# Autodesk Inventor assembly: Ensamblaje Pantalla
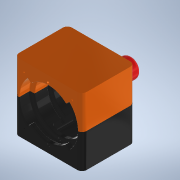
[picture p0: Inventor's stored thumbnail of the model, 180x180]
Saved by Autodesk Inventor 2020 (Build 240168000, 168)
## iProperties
Created: 2022-09
Part Number: Ensamblaje Pantalla
Document SubType Name: Assembly
Designer: SEBAS
Author: SEBAS
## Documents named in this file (3)
- D:\TRABAJO UNIVERSIDAD\PANTALLA LED INVENTOR\Ensamblaje Pantalla.iam
- D:\TRABAJO UNIVERSIDAD\MOLDER LATEAL\MOLDE LATERAL.ipt
- D:\TRABAJO UNIVERSIDAD\PIEZ\PIEZA SUPERIOR.ipt
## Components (3 placed, 2 different names)
1. MOLDE LATERAL:1 — Coincidencia:1, Coincidencia:2, Nivelación:4, Coincidencia:3, Nivelación:5, Nivelación:6, Coincidencia:4
2. MOLDE LATERAL:2 — Coincidencia:3, Nivelación:5, Nivelación:6, Coincidencia:4
3. PIEZA SUPERIOR:1 — Nivelación:1, Nivelación:2, Nivelación:3, Coincidencia:1, Coincidencia:2, Nivelación:4
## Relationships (10: Flush 6, Mate 4)
- Nivelación:1 [Flush]: PIEZA SUPERIOR:1
- Nivelación:2 [Flush]: PIEZA SUPERIOR:1
- Nivelación:3 [Flush]: PIEZA SUPERIOR:1
- Coincidencia:1 [Mate]: MOLDE LATERAL:1 ↔ PIEZA SUPERIOR:1
- Coincidencia:2 [Mate]: MOLDE LATERAL:1 ↔ PIEZA SUPERIOR:1
- Nivelación:4 [Flush]: MOLDE LATERAL:1 ↔ PIEZA SUPERIOR:1
- Coincidencia:3 [Mate]: MOLDE LATERAL:1 ↔ MOLDE LATERAL:2
- Nivelación:5 [Flush]: MOLDE LATERAL:1 ↔ MOLDE LATERAL:2
- Nivelación:6 [Flush]: MOLDE LATERAL:1 ↔ MOLDE LATERAL:2
- Coincidencia:4 [Mate]: MOLDE LATERAL:1 ↔ MOLDE LATERAL:2
